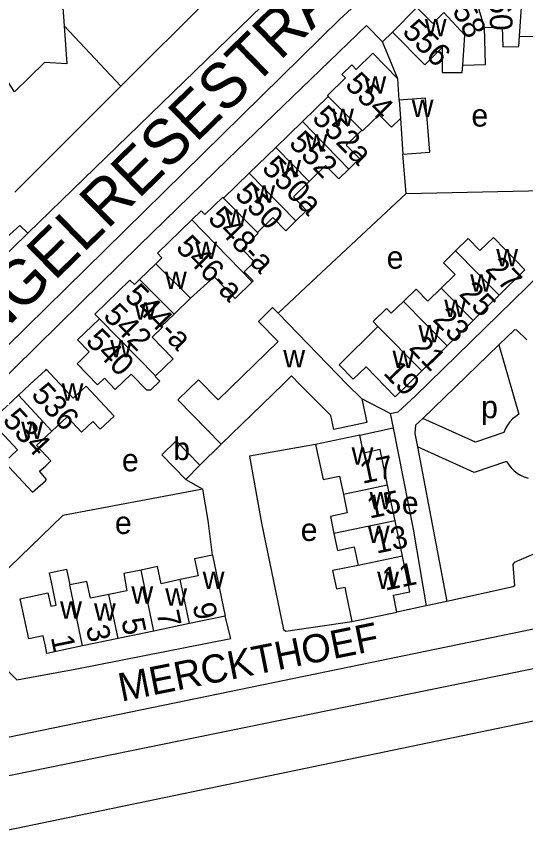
# Model space of a CAD drawing. Extents: x 162883 to 165538, y 383986 to 385172.
# Drawn here: x 163994.9 to 164085, y 384167.4 to 384315.2 of the extents above; entities that cross this region are included whole.
import ezdxf

# ---------------------------------------------------------------- set-up
doc = ezdxf.new("R2010")
doc.units = 0
for name, color, linetype in [('BLT_Basislijn', 7, 'Continuous'), ('BLT_Bebouwing', 7, 'Continuous'), ('BLT_Centroide', 7, 'Continuous'), ('BLT_Huisnummer', 7, 'Continuous'), ('BLT_Huisnummer_ tussenligend', 7, 'Continuous'), ('BLT_Huisnummer_reeks', 7, 'Continuous'), ('BLT_Onderdoorgang_en_onderverdeling', 7, 'Continuous'), ('BLT_Onderverdeling_panden', 7, 'Continuous'), ('BLT_Spoorlijn', 7, 'Continuous'), ('BLT_Straatnaam', 7, 'Continuous'), ('BLT_Straatnaam_hoofdweg', 7, 'Continuous')]:
    doc.layers.add(name, color=color, linetype=linetype)

msp = doc.modelspace()

# ---------------------------------------------------------------- linework, layer by layer
at = {"layer": 'BLT_Basislijn'}
for p, q in [((164033.81, 384323.31), (164013.39, 384302.89)), ((164003.33, 384313.56), (164013.39, 384302.89)), ((164062.42, 384304.21), (164059.74, 384310.76)), ((164013.39, 384302.89), (163994.61, 384284.11)), ((164063.93, 384283.89), (164063.3, 384290.84)), ((164048.03, 384269.01), (164063.93, 384283.89)), ((164080.34, 384257.01), (164066.84, 384243.99)), ((164080.34, 384257.01), (164083.89, 384244.74)), ((164061.09, 384244.88), (164056.04, 384247.48)), ((164055.73, 384241.01), (164061.6, 384242.32)), ((164027.38, 384235.71), (164031.16, 384239.4)), ((164065.9, 384238.93), (164071.11, 384211.55)), ((164024.87, 384233.17), (164027.9, 384231.44)), ((164150.83, 384212.71), (163969.22, 384175.66)), ((164071.11, 384211.55), (164067.45, 384210.74)), ((164067.45, 384210.74), (164062.26, 384209.61))]:
    msp.add_line(p, q, dxfattribs=at)
for points in [[(163964.42, 384228.4), (163986.24, 384250), (164052.16, 384314.79), (164056.26, 384318.57), (164060.48, 384321.02), (164065.34, 384323.67), (164071.72, 384327.14), (164076.99, 384329.2), (164083.5, 384330.4)], [(163996.88, 384276.8), (164040.36, 384319.07), (164052.17, 384331.03)], [(164059.74, 384310.76), (164056.87, 384313.63), (164032.27, 384289.87), (164016.59, 384274.64), (164006.24, 384264.42), (163967.06, 384225.86)], [(164059.74, 384310.76), (164061.48, 384312.49)], [(164061.09, 384244.88), (164062.5, 384245.17), (164065.53, 384247.95), (164095.17, 384276.86), (164095.17, 384277.18), (164092.06, 384280.8), (164088.28, 384284.4)], [(164063.93, 384283.89), (164088.28, 384284.4)], [(163996.88, 384276.8), (163995.5, 384278.19), (163975.8, 384260.54)], [(163977.91, 384258.34), (163996.88, 384276.8)], [(164041.21, 384262.63), (164048.03, 384269.01)], [(164085.28, 384257.93), (164083.53, 384259.61), (164083.1, 384259.67), (164080.34, 384257.01)], [(164061.09, 384244.88), (164061.6, 384242.32)], [(164083.89, 384244.74), (164083.31, 384244.34), (164082.77, 384243.88), (164082.3, 384243.36), (164081.88, 384242.8), (164081.53, 384242.18), (164081.22, 384241.46)], [(164066.84, 384243.99), (164065.59, 384242.79), (164065.45, 384241.28), (164065.9, 384238.93)], [(164081.22, 384241.46), (164076.22, 384239.76), (164066.84, 384243.99)], [(164061.6, 384242.32), (164065.15, 384224.32), (164067.45, 384210.74)], [(164047.84, 384239.38), (164036.17, 384237.27), (164038.27, 384225.41), (164042.21, 384206.57), (164042.62, 384206.28), (164054.29, 384207.95)], [(164081.69, 384236.34), (164075.96, 384234.4), (164065.9, 384238.93)], [(164081.69, 384236.34), (164082.08, 384235.74), (164082.52, 384235.2), (164083.03, 384234.71), (164083.59, 384234.28), (164084.19, 384233.92), (164084.83, 384233.62), (164085.5, 384233.41)], [(164027.9, 384231.44), (164003.06, 384226.79), (163984.22, 384208.51)], [(164029.58, 384219.73), (164028.81, 384225.86), (164027.9, 384231.44)], [(164111.98, 384230.83), (164083.06, 384218.41), (164082.81, 384218.06), (164083.09, 384214.28), (164082.86, 384214.12), (164071.11, 384211.55)], [(164116.02, 384212.73), (163993.66, 384187.45), (163993.19, 384187.45), (163960.99, 384219.5)], [(163984.22, 384208.51), (163994.93, 384197.66), (164005.58, 384199.58), (164032.87, 384204.99), (164031.84, 384208.94)]]:
    msp.add_lwpolyline(points, dxfattribs=at)
at = {"layer": 'BLT_Bebouwing'}
for p, q in [((164003.04, 384317.58), (164003.33, 384313.56)), ((164065.79, 384316.81), (164061.48, 384312.49)), ((164003.33, 384313.56), (164003.82, 384306.84)), ((164061.48, 384312.49), (164067.19, 384306.67)), ((164062.67, 384300.4), (164062.42, 384304.21)), ((164062.88, 384297.17), (164063.3, 384290.84)), ((164061.28, 384262.62), (164063.44, 384264.74)), ((164080.37, 384265.85), (164075.78, 384261.34)), ((164075.78, 384261.34), (164071.19, 384256.83)), ((164071.19, 384256.83), (164066.66, 384252.4)), ((164027.38, 384235.71), (164023.15, 384240.01)), ((164024.87, 384233.17), (164027.38, 384235.71)), ((164061.94, 384225.84), (164060.63, 384232.15)), ((164063.25, 384219.54), (164061.94, 384225.84)), ((164029.58, 384219.73), (164031.84, 384208.94)), ((164031.84, 384208.94), (164025.52, 384207.62)), ((164054.29, 384207.95), (164062.26, 384209.61)), ((164025.52, 384207.62), (164019.21, 384206.29)), ((164019.21, 384206.29), (164012.9, 384204.97)), ((164012.9, 384204.97), (164006.58, 384203.64))]:
    msp.add_line(p, q, dxfattribs=at)
for points in [[(164070.56, 384315.97), (164068.61, 384314.02), (164065.79, 384316.81)], [(164073.92, 384306.62), (164077.95, 384306.71), (164077.81, 384313.28)], [(164077.81, 384313.28), (164080.94, 384313.35), (164081.02, 384309.87), (164083.87, 384309.94), (164083.96, 384311.76)], [(164003.82, 384306.84), (163999.84, 384307.07), (163994.54, 384301.9), (163990.74, 384307.67), (163987.3, 384307.89), (163987.13, 384306.07), (163978.64, 384311.36)], [(164083.96, 384311.76), (164086.84, 384311.68), (164086.66, 384307.86), (164089.61, 384307.73)], [(164067.19, 384306.67), (164070.3, 384309.74), (164070.3, 384305.34), (164073.83, 384305.34), (164073.92, 384306.62)], [(164062.42, 384304.21), (164058.02, 384308.74), (164055.07, 384305.87), (164054.29, 384306.68), (164052.54, 384304.98), (164053.17, 384304.35), (164049.97, 384301.24), (164050.12, 384301.08)], [(164050.12, 384301.08), (164045.52, 384296.61)], [(164063.3, 384290.84), (164068.08, 384291.2), (164067.35, 384300.76), (164062.67, 384300.4)], [(164056.03, 384295.11), (164056.19, 384294.95), (164059.11, 384297.82), (164061.29, 384295.61), (164062.88, 384297.17)], [(164045.52, 384296.61), (164040.82, 384292.04)], [(164053.73, 384288.18), (164055.63, 384290.05), (164053.3, 384292.43), (164056.03, 384295.11)], [(164040.82, 384292.04), (164036.12, 384287.47)], [(164046.72, 384285.97), (164049.63, 384288.83), (164051.96, 384286.45), (164053.73, 384288.18)], [(164036.12, 384287.47), (164031.58, 384283.06)], [(164044.37, 384279), (164046.27, 384280.86), (164043.93, 384283.24), (164046.72, 384285.97)], [(164031.58, 384283.06), (164031.43, 384283.21), (164028.24, 384280.12), (164027.59, 384280.77), (164025.95, 384279.18)], [(164037.56, 384276.96), (164040.28, 384279.62), (164042.6, 384277.26), (164044.37, 384279)], [(164025.95, 384279.18), (164019.86, 384273.27), (164020.65, 384272.47), (164019.56, 384271.4)], [(164036.62, 384268.17), (164036.82, 384268.36), (164035.21, 384270), (164037.02, 384271.77), (164034.85, 384273.98), (164037.71, 384276.8), (164037.56, 384276.96)], [(164072.66, 384273.71), (164074.87, 384275.88), (164076.98, 384273.73), (164079.36, 384276.06), (164081.46, 384273.92), (164084.96, 384270.35), (164080.37, 384265.85)], [(164070.14, 384267.09), (164072.57, 384269.48), (164070.5, 384271.59), (164072.66, 384273.71)], [(164019.56, 384271.4), (164016.69, 384268.61)], [(164016.69, 384268.61), (164015.76, 384267.71), (164014.97, 384268.51), (164008.74, 384262.46), (164009.56, 384261.62)], [(164025.68, 384265.29), (164029.87, 384269.09), (164033.64, 384265.25), (164036.62, 384268.17)], [(164063.44, 384264.74), (164065.66, 384266.92), (164067.77, 384264.77), (164070.14, 384267.09)], [(164022.79, 384262.48), (164025.68, 384265.29)], [(164031.16, 384239.4), (164023.49, 384247.25), (164027.14, 384250.85), (164030.61, 384247.27), (164041.22, 384257.62), (164037.75, 384261.17), (164040.25, 384263.62)], [(164040.25, 384263.62), (164041.21, 384262.63)], [(164061.28, 384262.62), (164060.43, 384263.49), (164058.06, 384261.16), (164058.91, 384260.29)], [(164019.5, 384251.51), (164022.62, 384254.53), (164018.89, 384258.39), (164020.68, 384260.09), (164020.49, 384260.25), (164022.79, 384262.48)], [(164041.21, 384262.63), (164053.45, 384250), (164056.04, 384247.48)], [(164019.5, 384251.51), (164019.43, 384251.44), (164020.25, 384250.59), (164018.62, 384249.01), (164017.97, 384249), (164015.19, 384251.81), (164012.38, 384249.13), (164010.47, 384251.13), (164009.23, 384249.94), (164005.62, 384253.68), (164007.77, 384255.79), (164005.7, 384257.93), (164009.56, 384261.62)], [(164066.66, 384252.4), (164064.22, 384250), (164061.99, 384247.83), (164056.81, 384253.14), (164054.55, 384250.93), (164052.02, 384253.5), (164058.91, 384260.29)], [(164001.14, 384241.72), (164003.88, 384244.26), (164006.4, 384241.55), (164008.41, 384243.43), (164009.69, 384242.05), (164012.18, 384244.37), (164007.2, 384249.71), (164004.92, 384247.59), (164000.16, 384252.7), (164000, 384252.55), (163997.26, 384250), (163995.22, 384248.1)], [(164051.08, 384242.04), (164050.55, 384244.51), (164045.05, 384250), (164043.57, 384251.51), (164042.04, 384250), (164031.16, 384239.4)], [(163995.22, 384248.1), (163990.28, 384243.5), (163995.04, 384238.39), (163992.74, 384236.25), (163997.72, 384230.9), (164000, 384232.94), (164000.22, 384233.15), (163998.94, 384234.6), (164000, 384235.53), (164000.95, 384236.48), (163998.43, 384239.18), (164001.14, 384241.72)], [(164056.04, 384247.48), (164056.96, 384243.26), (164051.08, 384242.04)], [(164023.15, 384240.01), (164020.6, 384237.5), (164024.87, 384233.17)], [(164055.73, 384241.01), (164047.84, 384239.38)], [(164060.63, 384232.15), (164059.32, 384238.46), (164056.38, 384237.85), (164055.73, 384241.01)], [(164047.84, 384239.38), (164049.2, 384233.15), (164052.12, 384233.75), (164052.79, 384230.52)], [(164052.79, 384230.52), (164053.48, 384227.22), (164050.5, 384226.6), (164051.12, 384223.6)], [(164051.12, 384223.6), (164051.75, 384220.58), (164054.7, 384221.19), (164055.38, 384217.9)], [(164029.58, 384219.73), (164026.43, 384219.07), (164027.06, 384216.06), (164023.89, 384215.4)], [(164062.26, 384209.61), (164061.64, 384212.62), (164064.56, 384213.23), (164063.25, 384219.54)], [(164023.89, 384215.4), (164020.5, 384214.68), (164019.84, 384217.71), (164016.94, 384217.1)], [(164055.38, 384217.9), (164050.87, 384217.04), (164051.55, 384213.74), (164053.02, 384214.04), (164053.27, 384212.85), (164054.29, 384207.95)], [(164006.58, 384203.64), (164000.27, 384202.32), (164000, 384203.58), (163999.61, 384205.45), (163997.06, 384204.9), (163995.52, 384212.01), (164000.43, 384213.07), (164000.96, 384210.67), (164001.91, 384210.86), (164001.29, 384213.82), (164000.71, 384216.59), (164003.76, 384217.23), (164004.31, 384214.45)], [(164016.94, 384217.1), (164013.88, 384216.46), (164014.42, 384213.43), (164011.26, 384212.77)], [(164011.26, 384212.77), (164007.99, 384212.09), (164007.36, 384215.09), (164006.18, 384214.85), (164004.31, 384214.45)]]:
    msp.add_lwpolyline(points, dxfattribs=at)
at = {"layer": 'BLT_Onderdoorgang_en_onderverdeling'}
for p, q in [((164025.68, 384265.29), (164019.56, 384271.4)), ((164016.69, 384268.61), (164022.79, 384262.48))]:
    msp.add_line(p, q, dxfattribs=at)
at = {"layer": 'BLT_Onderverdeling_panden'}
for p, q in [((164077.81, 384313.28), (164075.09, 384322.34)), ((164083.96, 384311.76), (164084.65, 384321.68)), ((164070.56, 384315.97), (164074.29, 384311.93)), ((164073.92, 384306.62), (164074.29, 384311.93)), ((164056.03, 384295.11), (164050.12, 384301.08)), ((164062.67, 384300.4), (164062.88, 384297.17)), ((164053.73, 384288.18), (164045.52, 384296.61)), ((164046.72, 384285.97), (164040.82, 384292.04)), ((164044.37, 384279), (164036.12, 384287.47)), ((164037.56, 384276.96), (164031.58, 384283.06)), ((164036.62, 384268.17), (164025.95, 384279.18)), ((164080.37, 384265.85), (164072.66, 384273.71)), ((164075.78, 384261.34), (164070.14, 384267.09)), ((164071.19, 384256.83), (164063.44, 384264.74)), ((164009.56, 384261.62), (164019.5, 384251.51)), ((164066.66, 384252.4), (164058.91, 384260.29)), ((164001.14, 384241.72), (163995.22, 384248.1)), ((164060.63, 384232.15), (164052.79, 384230.52)), ((164061.94, 384225.84), (164051.12, 384223.6)), ((164063.25, 384219.54), (164055.38, 384217.9)), ((164019.21, 384206.29), (164016.94, 384217.1)), ((164006.58, 384203.64), (164004.31, 384214.45)), ((164025.52, 384207.62), (164023.89, 384215.4)), ((164012.9, 384204.97), (164011.26, 384212.77))]:
    msp.add_line(p, q, dxfattribs=at)
at = {"layer": 'BLT_Spoorlijn'}
msp.add_lwpolyline([(164137.67, 384200.96), (163976.02, 384167.4)], dxfattribs=at)

# ---------------------------------------------------------------- texts
at = {"layer": 'BLT_Centroide'}
for s, p in [('w', (164067.21, 384311.75)), ('w', (164056.51, 384301.56)), ('w', (164064.89, 384297.42)), ('w', (164050.78, 384295.81)), ('e', (164075.47, 384295.72)), ('w', (164046.12, 384291.28)), ('w', (164041.42, 384286.73)), ('w', (164036.82, 384282.22)), ('w', (164031.83, 384277.97)), ('w', (164026.55, 384272.22)), ('e', (164060.46, 384270.53)), ('w', (164079.87, 384270.94)), ('w', (164021.19, 384266.94)), ('w', (164075.25, 384266.47)), ('w', (164070.66, 384261.97)), ('w', (164015.77, 384261.47)), ('w', (164066.08, 384257.45)), ('w', (164011.47, 384254.84)), ('w', (164042.14, 384253.02)), ('w', (164061.49, 384252.94)), ('w', (164002.87, 384247.12)), ('p', (164077.19, 384244.02)), ('w', (163995.72, 384240.31)), ('b', (164022.65, 384236.61)), ('w', (164054.25, 384235.78)), ('e', (164013.56, 384234.6)), ('w', (164057.43, 384227.88)), ('e', (164063.14, 384227.02)), ('e', (164012.32, 384223.49)), ('e', (164045.23, 384222.25)), ('w', (164057.12, 384221.88)), ('w', (164027.86, 384213.73)), ('w', (164058.77, 384213.75)), ('w', (164015.23, 384211.11)), ('w', (164021.23, 384210.78)), ('w', (164002.61, 384208.45)), ('w', (164008.61, 384208.14))]:
    msp.add_text(s, height=4, dxfattribs=at).set_placement(p)
at = {"layer": 'BLT_Huisnummer'}
for s, rotation, p in [('560', 271.2507, (164078.58, 384321.61)), ('558', 297.3654, (164070.64, 384318.98)), ('556', 314.9901, (164063.04, 384312.37)), ('554', 314.9869, (164052.89, 384302.98)), ('552a', 314.9878, (164047.05, 384297.05)), ('552', 314.9878, (164042.96, 384292.6)), ('550a', 314.9756, (164038.16, 384288.16)), ('550', 314.9756, (164033.36, 384283.49)), ('27', 314.4418, (164077.76, 384270.3)), ('23', 314.4397, (164068.47, 384261.39)), ('540', 314.846, (164006.94, 384257.52)), ('19', 313.8231, (164059.7, 384251.95)), ('536', 312.8835, (163997.31, 384248.05)), ('534', 312.852, (163992.25, 384243.53)), ('17', 11.7342, (164056.16, 384232.38)), ('11', 11.7362, (164060.19, 384213.43)), ('9', 281.8523, (164026.04, 384210.91)), ('5', 281.8524, (164013.44, 384208.22)), ('1', 281.7471, (164000.94, 384205.21))]:
    msp.add_text(s, height=4, rotation=rotation, dxfattribs=at).set_placement(p)
at = {"layer": 'BLT_Huisnummer_ tussenligend'}
for s, rotation, p in [('25', 314.4397, (164073.13, 384265.93)), ('21', 313.8231, (164064.25, 384256.38)), ('15', 11.7362, (164057.42, 384226.2)), ('13', 11.7362, (164058.64, 384219.99)), ('7', 281.8524, (164019.65, 384209.57)), ('3', 281.7471, (164007.17, 384206.98))]:
    msp.add_text(s, height=4, rotation=rotation, dxfattribs=at).set_placement(p)
at = {"layer": 'BLT_Huisnummer_reeks'}
for s, rotation, p in [('548-a', 314.1065, (164028.59, 384279.27)), ('546-a', 315, (164022.91, 384274.09)), ('544-a', 314.8361, (164013.82, 384265.47)), ('542', 314.8361, (164010.06, 384261.99))]:
    msp.add_text(s, height=4, rotation=rotation, dxfattribs=at).set_placement(p)
at = {"layer": 'BLT_Straatnaam'}
msp.add_text('MERCKTHOEF', height=5, rotation=11.3634, dxfattribs=at).set_placement((164013.47, 384193.76))
at = {"layer": 'BLT_Straatnaam_hoofdweg'}
msp.add_text('TONGELRESESTRAAT', height=8, rotation=44.3284, dxfattribs=at).set_placement((163979.48, 384246.63))

doc.saveas('drawing.dxf')
